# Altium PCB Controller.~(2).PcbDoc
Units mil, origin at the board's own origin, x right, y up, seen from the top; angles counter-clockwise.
Board outline not stored, 2 copper layers (Top Layer, Bottom Layer); 7 components, 6 nets, 20 pads, 0 vias.
Unrouted connection lines stored in the file: 10.
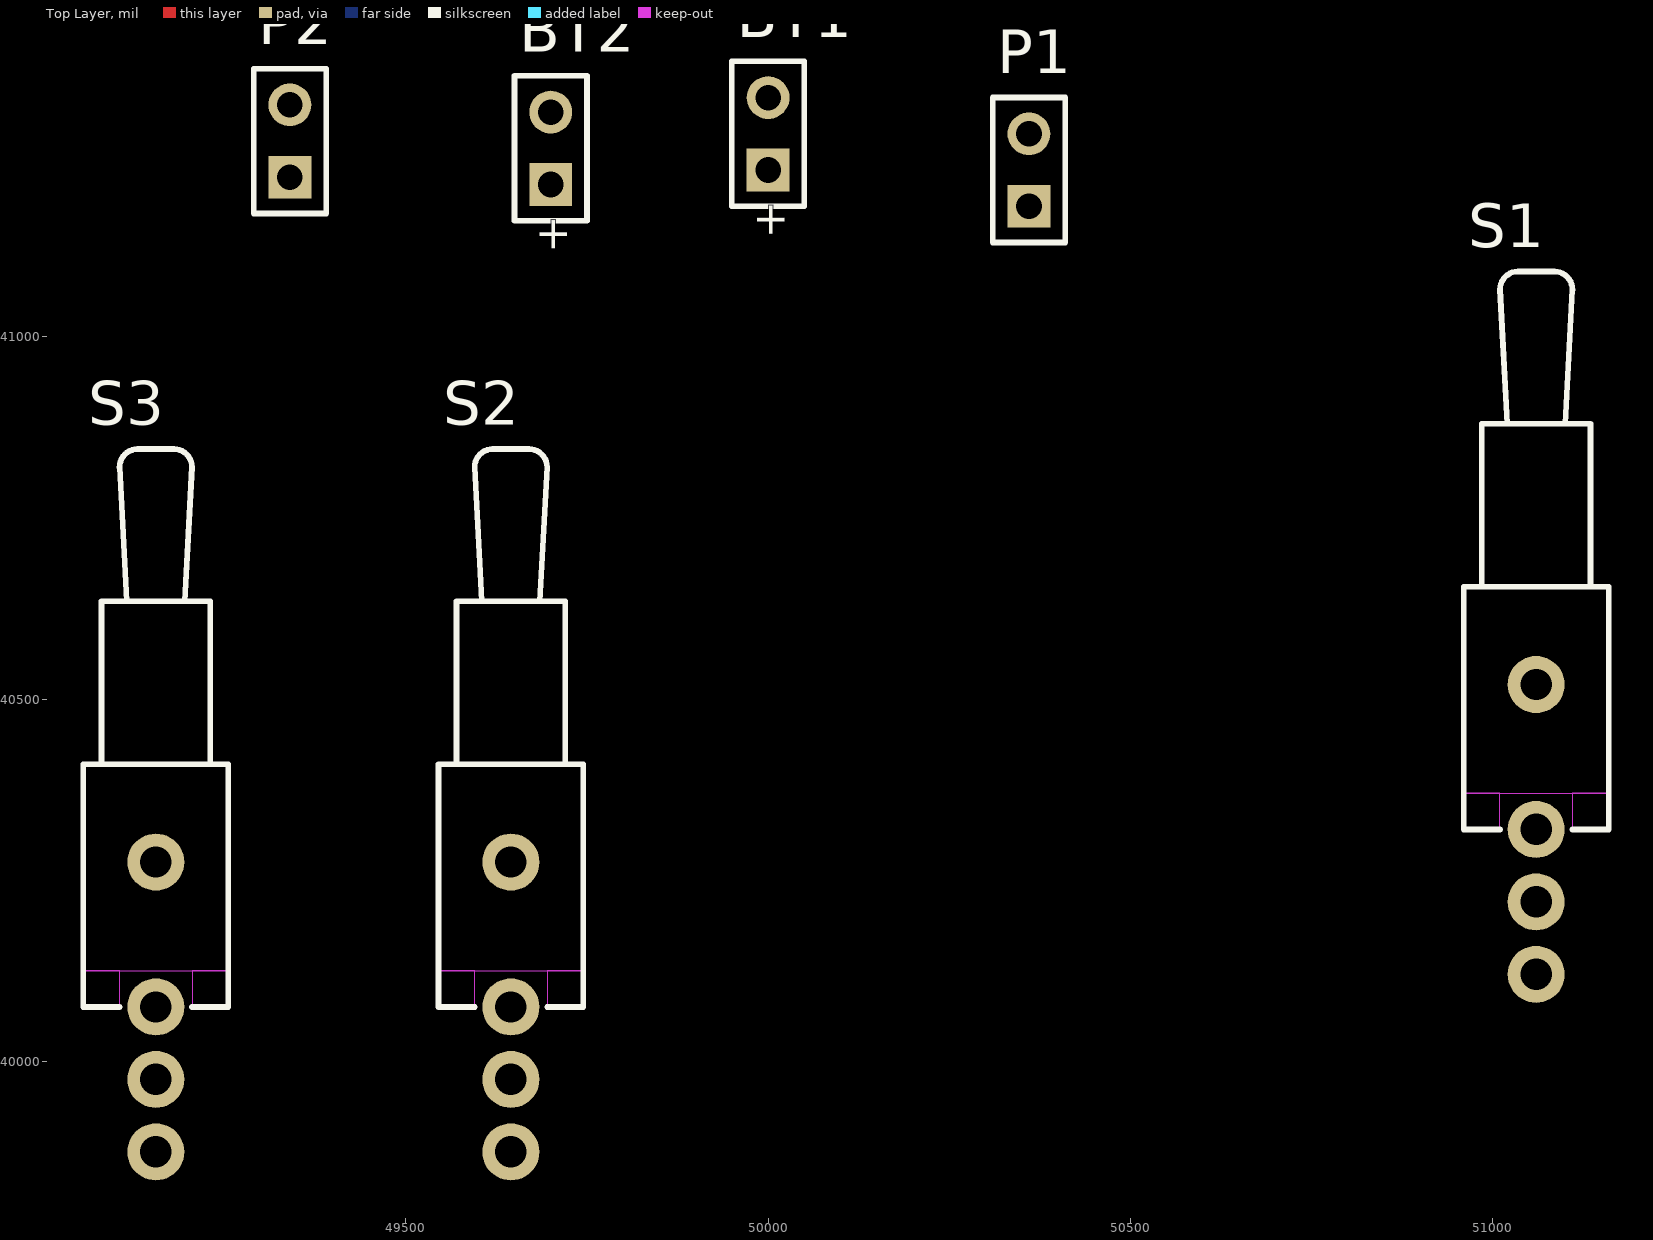
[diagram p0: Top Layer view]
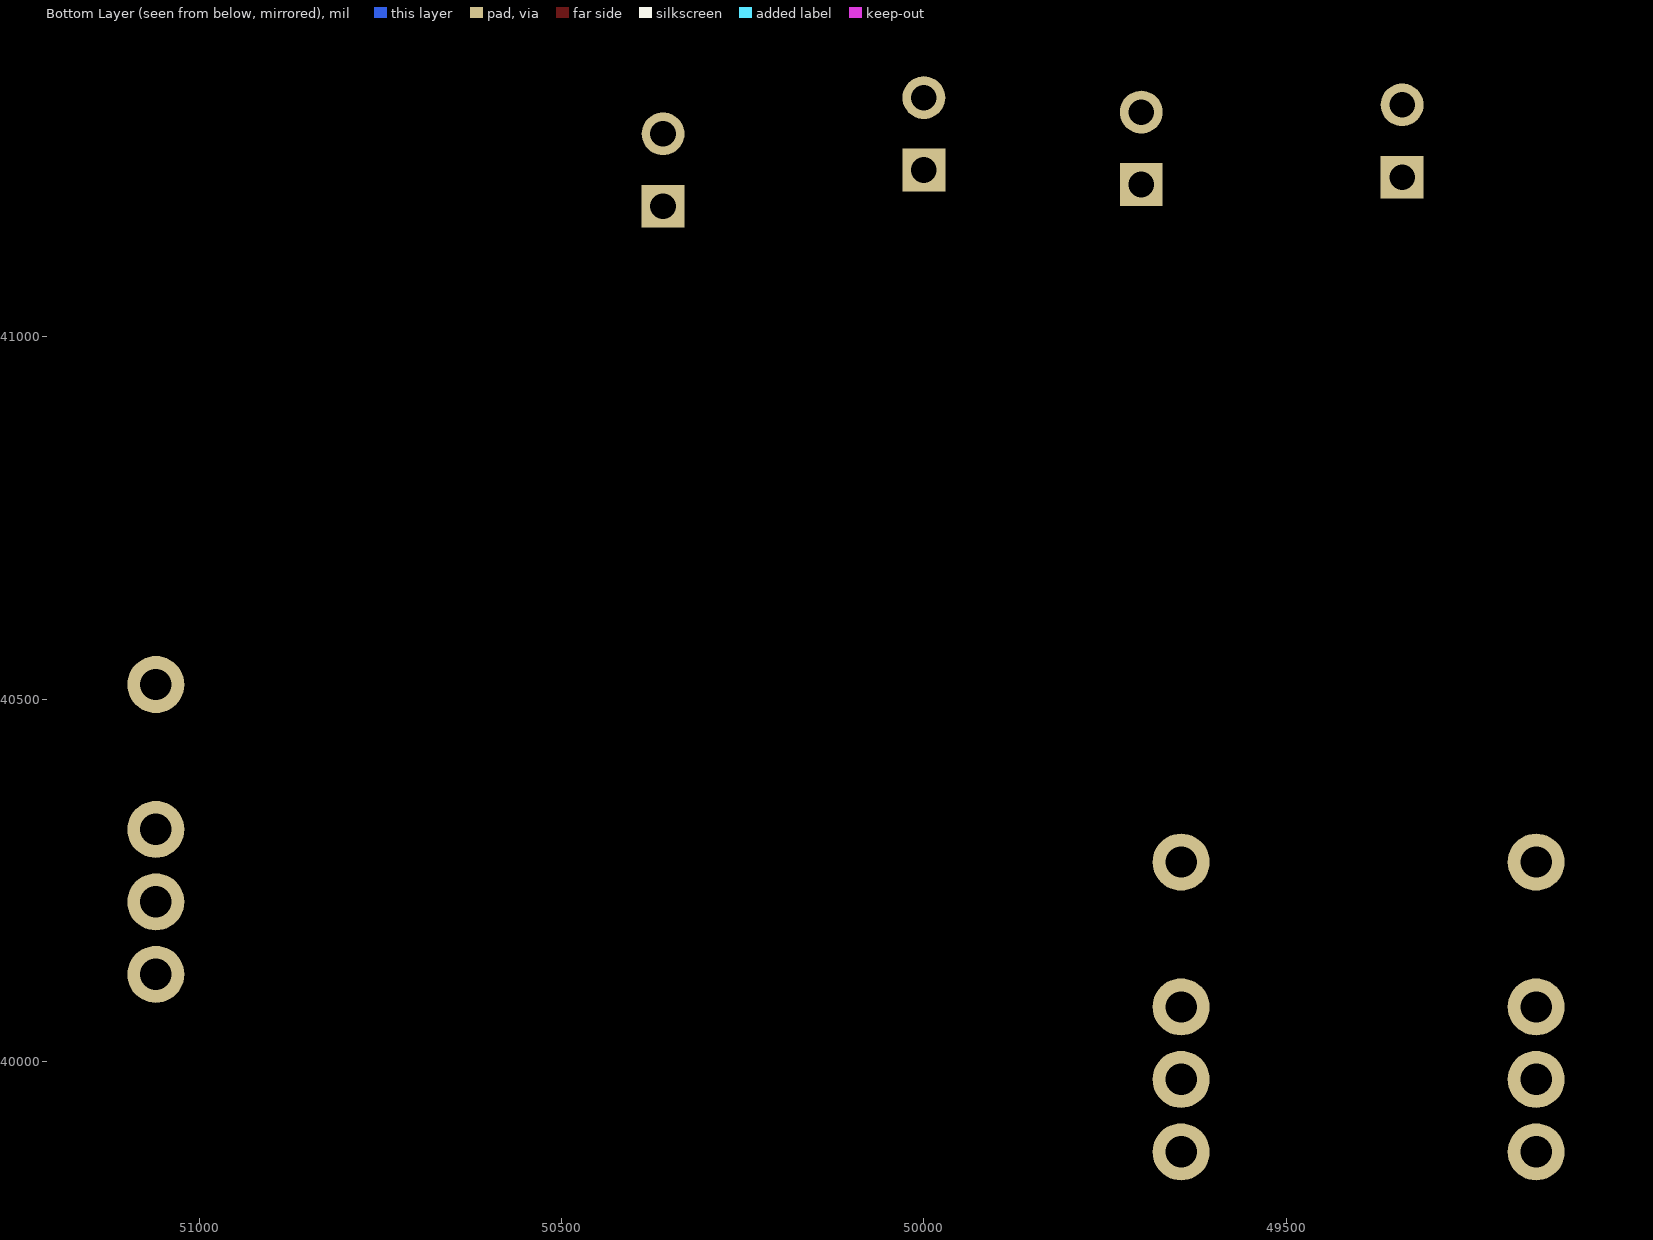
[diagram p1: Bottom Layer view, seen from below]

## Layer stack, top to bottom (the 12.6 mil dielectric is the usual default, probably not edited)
Top Layer: signal copper 1.4
Dielectric: dielectric 12.6, FR-4, Dk 4.8
Bottom Layer: signal copper 1.4

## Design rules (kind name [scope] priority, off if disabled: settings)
Clearance [All] p1: gap=10
PolygonConnect [All] p1: connectstyle=Relief reliefconductorwidth=10 reliefentries=4 polygonreliefangle="90 Angle"
RoomDefinition Controller [InComponentClass('Controller')] p1: confinementstyle=ConfineIn formatcopy=TRUE lockcomponents=FALSE outline 48875,39825 50380,39825 50380,40955 48875,40955
RoutingVias [All] p1: holewidth=28 width=50 viastyle="Through Hole" minholewidth=28 minwidth=50 maxholewidth=28 maxwidth=50
SilkscreenOverComponentPads [All] p1: minsilkscreentomaskgap=10
SolderMaskExpansion [All] p1: expansion=4
Width [All] p1: maxlimit=10 minlimit=10 preferedwidth=10
27 further rules are at their usual default settings.

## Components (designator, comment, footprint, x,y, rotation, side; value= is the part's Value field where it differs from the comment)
BT1 "Battery" BAT-2 50000,41280 r90 top
BT2 "Battery" BAT-2 49700,41260 r90 top
P1 "Header 2" HDR1X2 50360,41180 r90 top
P2 "Header 2" HDR1X2 49340,41220 r90 top
S1 "SW-SPDT" TL36WW15050 51060,40320 r90 top
S2 "SW-SPDT" TL36WW15050 49645,40075 r90 top
S3 "SW-SPDT" TL36WW15050 49155,40075 r90 top

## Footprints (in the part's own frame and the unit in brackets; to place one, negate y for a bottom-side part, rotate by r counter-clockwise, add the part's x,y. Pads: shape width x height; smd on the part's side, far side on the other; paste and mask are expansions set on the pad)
BAT-2 [mm] "Multicell Battery; 2 Leads"
  rect 1.5x1.5 hole 0.9: 1(-1.27,0)
  round 1.5 hole 0.9: 2(1.27,0)
  silkscreen extent -2.54,-1.27 2.54,1.27
HDR1X2 [mm] "Connector; Header; 2 Position"
  rect 1.5x1.5 hole 0.9: 1(0,0)
  round 1.5 hole 0.9: 2(2.54,0)
  silkscreen extent -1.27,-1.27 3.81,1.27
TL36WW15050 [mm] "SPDT Subminiature Toggle Switch, Right Angle Mounting, Vertical Actuation"
  round 2 hole 1.1: 1(0,0) 2(-2.54,0) 3(-5.08,0) M(5.08,0)
  Top Layer keep-out region: 0,-1.27 0,-2.54 1.27,-2.54 1.27,-1.27
  Top Layer keep-out region: 0,2.54 0,1.27 1.27,1.27 1.27,2.54
  Top Layer keep-out region: 1.27,2.54 1.27,-2.54 8.509,-2.54 8.509,2.54
  silkscreen extent 0,-2.54 19.56,2.54

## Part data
BT1 BT2: "Multicell Battery"
P1 P2: "Header, 2-Pin"
S1 S2 S3: "SPDT Subminiature Toggle Switch, Right Angle Mounting, Vertical Actuation"

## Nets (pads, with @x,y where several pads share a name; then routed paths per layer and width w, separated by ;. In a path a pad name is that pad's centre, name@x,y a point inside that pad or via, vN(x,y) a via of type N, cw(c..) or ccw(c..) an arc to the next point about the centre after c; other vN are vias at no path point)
NetBT1_1: BT1.1 S1.3 S2.3 S3.3
NetBT1_2: BT1.2 BT2.1 P2.1
NetBT2_2: BT2.2 S1.1 S3.1
NetP1_1: P1.1 S2.2
NetP1_2: P1.2 S1.2
NetP2_2: P2.2 S3.2
pads on no net: S1.M S2.1 S2.M S3.M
